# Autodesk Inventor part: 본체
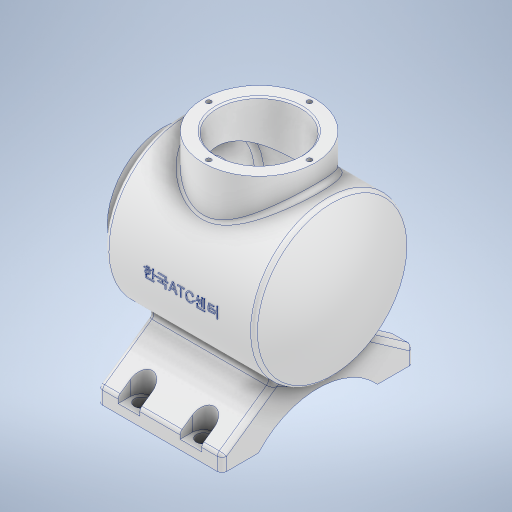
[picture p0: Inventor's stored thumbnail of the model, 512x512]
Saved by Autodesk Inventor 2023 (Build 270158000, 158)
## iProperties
Created: 2023-12
Part Number: 본체
Material: 알루미늄 6061
Document SubType Name: Modeling
Designer: asung
Density: 2.7 g/cm^3
Appearance: 알루미늄 - 평지
Mass: 1296.71 g
Surface Area: 1060.45 cm^2
Volume: 480.264 cm^3
Author: asung
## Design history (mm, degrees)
sketch "스케치1"
  geometry: L1 (0, 0)-(120, 0); L2 (0, 0)-(0, 36); L3 (0, 36)-(12, 36); L4 (12, 36)-(12, 50); L5 (12, 50)-(108.336, 50); L6 (0, 0)-(0, -36); L7 (0, -36)-(12, -36); L8 (12, -50)-(108.336, -50); L9 (12, -36)-(12, -50); L10 (0, 0)-(0, 27); L11 (0, 27)-(19, 27); L12 (19, 27)-(19, 43); L13 (19, 43)-(103.887, 43); A1 r 113 centre (7, 0) between (108.336, -50) and (108.336, 50); A2 r 106 centre (7, 0) between (113, 0) and (103.887, 43); 1 further point
  constraints: 26 end point, 6 perpendicular, 6 point on circle, 3 symmetric about line, 2 centre point, 2 point on line, 1 horizontal, 1 vertical
  dimensions: "d0" = 120 distance of L1.end L1.start; "d1" = 36 distance of L1.start L2.end; "d3" = 100 diameter of L5 L1; "d5" = 113 radius of A1; "d6" = 120 horizontal distance of point (120, 0) L2.end; "d7" = 108 horizontal distance of L1.end L4.end; "d8" = 27 distance of L1.start L10.end; "d9" = 19 distance of L10.end L11.end; "d10" = 86 diameter of L13 L1; "d11" = 7 radial gap between concentric circles of A1 A2; "d12" = 7 radial gap between concentric circles of A1 A2 (derived)
revolve "회전1" sketch "스케치1" stored, may be unused: angle "d13" = 360 deg
fillet "모깎기1" dims "d14" = 3
sketch "스케치3" dims "d15" = 65
  geometry: C1 r 27 at (0, 0) reference; C2 r 36 at (0, 0) reference; 3 further points
  constraints: 1 coincident, 1 vertical alignment, 2 other
hole "구멍1" sketch "스케치3" at (0, 32.5) diameter "d16" = 3.242; stored, may be unused: countersink angle "d20" = 90 deg, drill point angle "d22" = 118 deg; dims "d17" = 8, "d18" = 4, "d19" = 2, "d21" = 10
node "작업 평면1"
sketch "스케치4"
  geometry: L1 (0, 36)-(0, -36) reference; C1 r 36 at (-62, 0); 2 further points
  constraints: 1 centre point, 1 horizontal alignment, 1 midpoint
  dimensions: "d27" = 72 diameter of C1; "d28" = 62 distance from line of C1.centre L1
extrude "돌출1" join sketch "스케치4" stored distance "d29" = 10; taper "d30" = 0 deg
sketch "스케치5"
  geometry: C1 r 36 at (0, 0) reference; 2 further points
  constraints: 1 coincident
hole "구멍2" sketch "스케치5" at (0, 0) diameter "d31" = 54; stored, may be unused: countersink angle "d35" = 90 deg, drill point angle "d37" = 0 deg; dims "d32" = 8, "d33" = 4, "d34" = 2, "d36" = 50
sketch "스케치6" dims "d38" = 65
  geometry: C1 r 27 at (0, 0) reference; C2 r 36 at (0, 0) reference; 3 further points
  constraints: 1 coincident, 1 vertical alignment, 2 other
hole "구멍3" sketch "스케치6" at (0, 32.5) diameter "d39" = 3.242; stored, may be unused: countersink angle "d43" = 90 deg, drill point angle "d45" = 118 deg; dims "d40" = 8, "d41" = 4, "d42" = 2, "d44" = 10
chamfer "모따기1" distance "d49" = 1; stored, may be unused: second distance "d50" = 2, angle "d51" = 45 deg
fillet "모깎기2" dims "d52" = 3
node "작업 평면2"
sketch "스케치7"
  geometry: L1 (0, 0)-(0, -77); L2 (-38.5, -77)-(38.5, -77); L3 (38.5, -77)-(62, -77); L4 (62, -77)-(62, -67); L5 (62, -67)-(26.694, -42.278); L6 (-38.5, -77)-(-62, -77); L7 (-62, -77)-(-62, -67); L8 (-62, -67)-(-26.694, -42.278); C1 r 42.236 at (0, 0) reference; A1 r 50 centre (0, 0) between (26.694, -42.278) and (-26.694, -42.278) reference; A2 r 52.096 centre (0, -112.096) between (38.5, -77) and (-38.5, -77); 2 further points
  constraints: 16 end point, 5 point on circle, 3 horizontal, 2 perpendicular, 1 centre point, 1 midpoint, 1 vertical
  dimensions: "d54" = 77 distance of L1.end L1.start; "d55" = 77 distance of L2.start L2.end; "d57" = 17 distance of L1.end point (0, -60); "d58" = 23.5 distance of L2.end L3.end; "d59" = 10 distance of L3.end L4.end; "d60" = 55 deg angle of L4 L5; "d61" = 23.5 distance of L2.start L6.end; "d62" = 10 distance of L6.end L7.end; "d64" = 55 deg angle of L8 L7
extrude "돌출2" join sketch "스케치7" distance "d65" = 80; taper "d66" = 0 deg
sketch "스케치8"
  geometry: L1 (0, -100.5)-(0, -77) reference; L2 (0, -100.5)-(80, -100.5) reference; L3 (80, -77)-(80, -100.5) reference; L4 (0, -77)-(80, -77) reference; L5 (0, 0)-(0, 23.5) reference; L6 (0, 0)-(80, 0) reference; L7 (80, 23.5)-(80, 0) reference; L8 (0, 23.5)-(80, 23.5) reference; L9 (0, -77)-(0, 0) reference; L10 (0, -77)-(80, -77) reference; L11 (80, 0)-(80, -77) reference; L12 (0, 0)-(80, 0) reference; L13 (40, -100.5)-(40, -38.5); L14 (60, -92.5)-(20, -92.5); L15 (20, -92.5)-(20, 15.5); L16 (20, 15.5)-(60, 15.5); L17 (60, 15.5)-(60, -92.5); L18 (60, -92.5)-(20, 15.5); L19 (20, -92.5)-(60, 15.5); 1 further point
  constraints: 14 end point, 3 midpoint, 2 parallel, 1 horizontal, 1 perpendicular, 1 vertical
  dimensions: "d67" = 62 distance of L13.start L13.end; "d68" = 40 distance of L15.end L16.end; "d69" = 108 distance of L14.end L15.end
hole "구멍4" sketch "스케치8" at (20, -92.5), (60, -92.5), (60, 15.5), (20, 15.5) diameter "d70" = 9; stored, may be unused: countersink angle "d74" = 90 deg, drill point angle "d76" = 0 deg; dims "d71" = 8, "d72" = 4, "d73" = 2, "d75" = 6
node "작업 평면3"
sketch "스케치9"
  geometry: L1 (0, 29.983)-(80, 29.983) reference; L2 (80, 29.983)-(80, 0) reference; L3 (80, 0)-(0, 0) reference; L4 (0, 0)-(0, 29.983) reference; L5 (0, 124)-(80, 124) reference; L6 (80, 124)-(80, 94.017) reference; L7 (80, 94.017)-(0, 94.017) reference; L8 (0, 94.017)-(0, 124) reference; C1 r 4.5 at (60, 116) reference; C2 r 4.5 at (20, 8) reference; C3 r 4.5 at (60, 8) reference; C4 r 4.5 at (20, 116) reference; 1 further point
  node "절단 모서리 투영2"
sketch "스케치10"
  geometry: L1 (0, 124)-(80, 124) reference; L2 (0, 124)-(0, 88.694) reference; L3 (13, 116)-(13, 124); L4 (27, 116)-(27, 124); L5 (20, 116)-(60, 116); L6 (53, 116)-(53, 124); L7 (67, 116)-(67, 124); L8 (0, 23.5)-(0, 100.5) reference; L9 (0, 88.694)-(0, 35.306) reference; L10 (0, 62)-(-34.043, 62); L11 (13, 8)-(13, 0); L12 (27, 8)-(27, 0); L13 (53, 8)-(53, 0); L14 (67, 8)-(67, 0); L15 (13, 0)-(13, -7.523); L16 (13, -7.523)-(27, -7.523); L17 (27, -7.523)-(27, 0); L18 (53, 0)-(53, -11.643); L19 (53, -11.643)-(67, -11.643); L20 (67, -11.643)-(67, 0); A1 r 7 centre (20, 116) between (13, 116) and (27, 116); A2 r 7 centre (60, 116) between (53, 116) and (67, 116); A3 r 7 centre (20, 8) between (27, 8) and (13, 8); A4 r 7 centre (60, 8) between (67, 8) and (53, 8); 3 further points
  constraints: 32 end point, 10 symmetric about line, 8 point on circle, 5 perpendicular, 4 centre point, 4 vertical, 2 horizontal, 2 point on line, 1 midpoint, 2 other
  dimensions: "d85" = 14 diameter of A1; "d86" = 8 distance from line of L5.start L1; "d87" = 20 distance from line of L5.start L2; "d88" = 14 distance between parallel lines of L4 L3; "d89" = 40 distance of L5.start L5.end; "d90" = 14 diameter of A2; "d91" = 14 distance between parallel lines of L7 L6
extrude "돌출3" cut sketch "스케치10" distance "d92" = 30; taper "d93" = 0 deg
fillet "모깎기3" dims "d94" = 3
fillet "모깎기4" dims "d95" = 3
node "작업 평면4"
sketch "스케치11"
  geometry: L1 (-60.168, -36)-(-60.168, 36) reference; 3 further points
  constraints: 1 horizontal alignment, 1 midpoint, 1 other
  dimensions: "d96" = 62 distance from line of point (1.832, 0) L1
feature "엠보싱1" sketch "스케치11" dims "d0" = 120, "d1" = 36, "d3" = 100, "d5" = 113, "d6" = 120, "d7" = 108, "d8" = 27, "d9" = 19, "d10" = 86, "d11" = 7, "d12" = 7 (derived), "d14" = 3, "d97" = 0.5, "d98" = 0
node "솔리드1"
pattern_circular "원형 패턴1" dims angle "d24" = 360 deg
pattern_circular "원형 패턴2" dims angle "d47" = 360 deg
node "투영된 루프1"
node "투영된 루프2"
node "투영된 루프3"
node "투영된 루프4"
node "투영된 루프5"
node "절단 모서리 투영1"
feature "A9D066F2-1C7D-4E18-AEED-F7BC21143FA4" dims "d31" = 54, "d32" = 8, "d33" = 4, "d34" = 2, "d35" = 90 deg, "d36" = 50, "d37" = 0
other parameters: "d26" = 65, "d63" = 55 deg, "d77" = -6
